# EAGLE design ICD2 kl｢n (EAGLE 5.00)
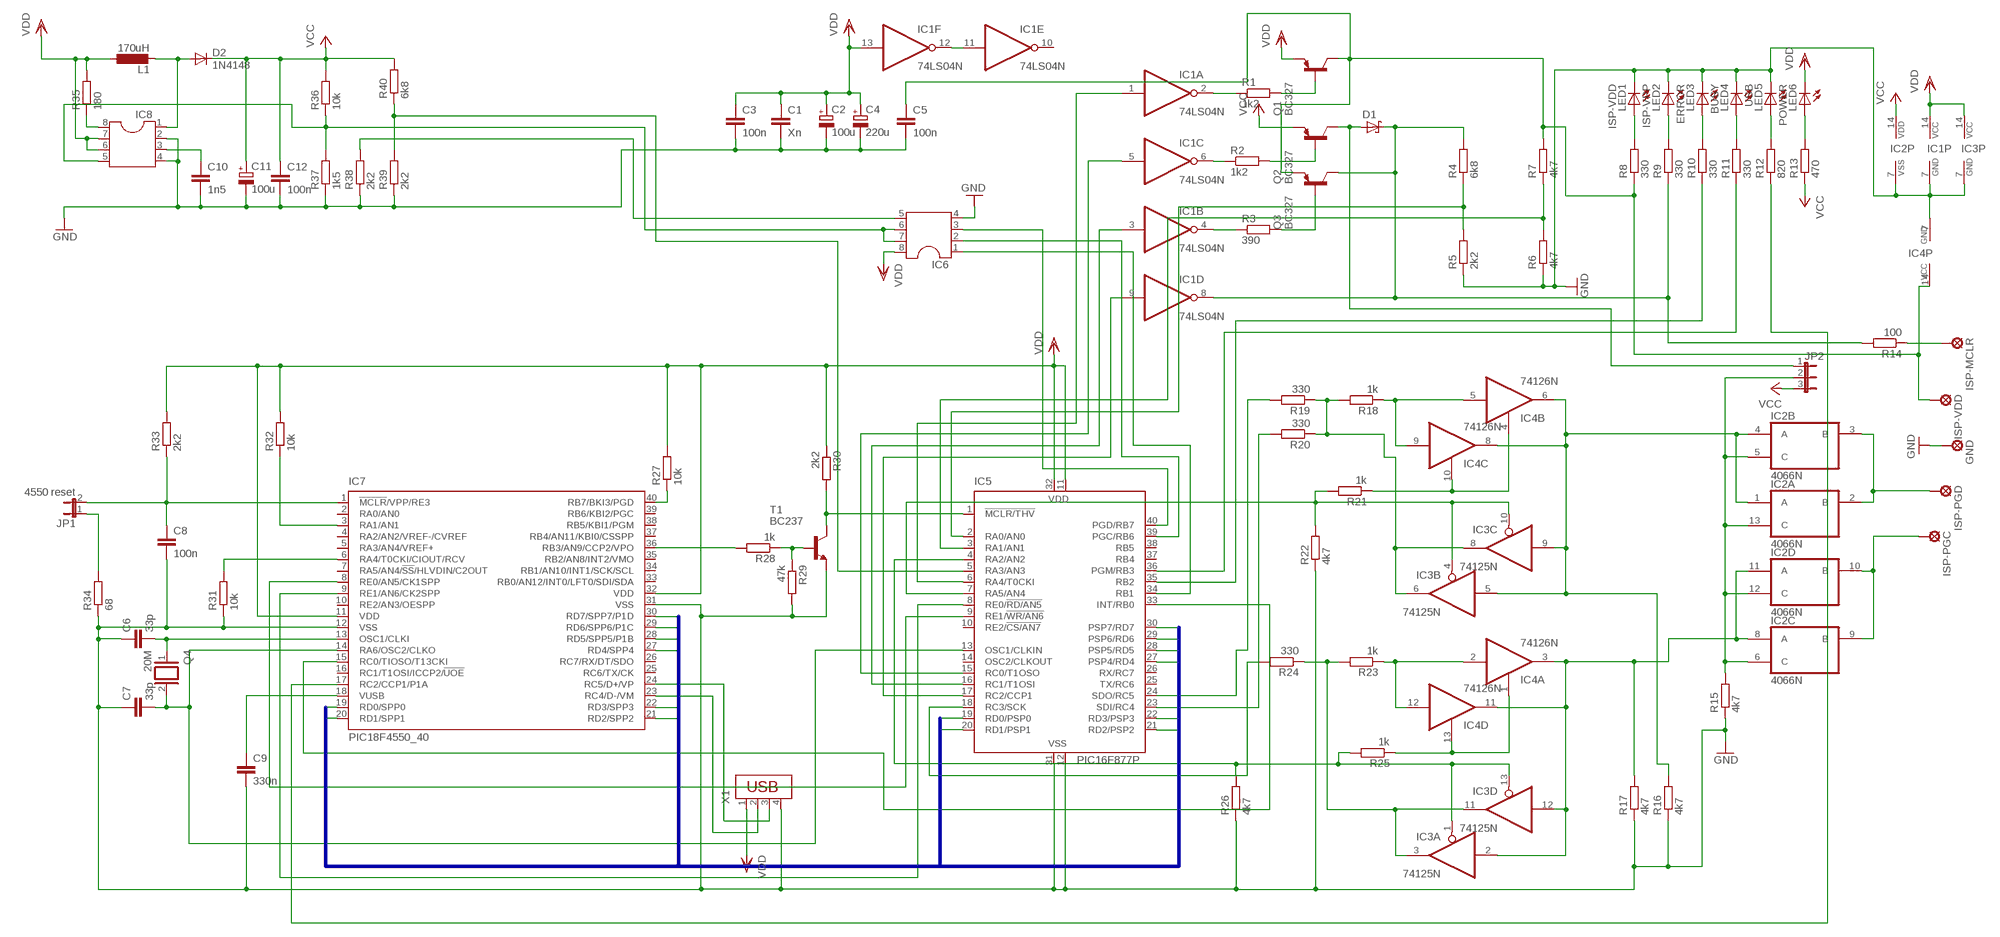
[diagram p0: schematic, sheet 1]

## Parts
C1  Xn  C5/3.5  [C5B3.5]
C2  100u  CPOL-EUE5-6  [E5-6]
C3  100n  C5/3.5  [C5B3.5]
C4  220u  CPOL-EUE5-6  [E5-6]
C5  100n  C5/3.5  [C5B3.5]
C6  33p  C5/3.5  [C5B3.5]
C7  33p  C5/3.5  [C5B3.5]
C8  100n  C5/3.5  [C5B3.5]
C9  330n  C5/3.5  [C5B3.5]
C10  1n5  C5/3.5  [C5B3.5]
C11  100u  CPOL-EUE5-6  [E5-6]
C12  100n  C5/3.5  [C5B3.5]
D1  SCHOTTKY-DIODEF126Z12  [F126Z12]
D2  1N4148  [DO35-10]
GND  LSP11  [LSP11]
IC1  74LS04N  [DIL14]
IC2  4066N  [DIL14]
IC3  74125N  [DIL14]
IC4  74126N  [DIL14]
IC5  PIC16F877P  [DIL40]
IC6  DIL8  [DIL08]
IC7  PIC18F4550_40  [DIL40]
IC8  DIL8  [DIL08]
ISP-MCLR  LSP11  [LSP11]
ISP-PGC  LSP11  [LSP11]
ISP-PGD  LSP11  [LSP11]
ISP-VDD  LSP11  [LSP11]
JP1  4550 reset  JP1E  [JP1]
JP2  JP2E  [JP2]
L1  170uH  L-EU0207/10  [0207/10]
LED1  ISP-VDD  LED5MM  [LED5MM]
LED2  ISP-VPP  LED5MM  [LED5MM]
LED3  ERROR  LED5MM  [LED5MM]
LED4  BUSY  LED5MM  [LED5MM]
LED5  USB  LED5MM  [LED5MM]
LED6  POWER  LED5MM  [LED5MM]
Q1  BC327  [TO92-EBC]
Q2  BC327  [TO92-EBC]
Q3  BC327  [TO92-EBC]
Q4  20M  XTAL/S  [QS]
R1  1k2  R-EU_0207/10  [0207/10]
R2  1k2  R-EU_0207/10  [0207/10]
R3  390  R-EU_0207/10  [0207/10]
R4  6k8  R-EU_0207/10  [0207/10]
R5  2k2  R-EU_0207/10  [0207/10]
R6  4k7  R-EU_0207/10  [0207/10]
R7  4k7  R-EU_0207/10  [0207/10]
R8  330  R-EU_0207/10  [0207/10]
R9  330  R-EU_0207/10  [0207/10]
R10  330  R-EU_0207/10  [0207/10]
R11  330  R-EU_0207/10  [0207/10]
R12  820  R-EU_0207/10  [0207/10]
R13  470  R-EU_0207/10  [0207/10]
R14  100  R-EU_0207/10  [0207/10]
R15  4k7  R-EU_0207/10  [0207/10]
R16  4k7  R-EU_0207/10  [0207/10]
R17  4k7  R-EU_0207/10  [0207/10]
R18  1k  R-EU_0207/10  [0207/10]
R19  330  R-EU_0207/10  [0207/10]
R20  330  R-EU_0207/10  [0207/10]
R21  1k  R-EU_0207/10  [0207/10]
R22  4k7  R-EU_0207/10  [0207/10]
R23  1k  R-EU_0207/10  [0207/10]
R24  330  R-EU_0207/10  [0207/10]
R25  1k  R-EU_0207/10  [0207/10]
R26  4k7  R-EU_0207/10  [0207/10]
R27  10k  R-EU_0207/10  [0207/10]
R28  1k  R-EU_0207/10  [0207/10]
R29  47k  R-EU_0207/10  [0207/10]
R30  2k2  R-EU_0207/10  [0207/10]
R31  10k  R-EU_0207/10  [0207/10]
R32  10k  R-EU_0207/10  [0207/10]
R33  2k2  R-EU_0207/10  [0207/10]
R34  68  R-EU_0207/10  [0207/10]
R35  180  R-EU_0207/10  [0207/10]
R36  10k  R-EU_0207/10  [0207/10]
R37  1k5  R-EU_0207/10  [0207/10]
R38  2k2  R-EU_0207/10  [0207/10]
R39  2k2  R-EU_0207/10  [0207/10]
R40  6k8  R-EU_0207/10  [0207/10]
T1  BC237  [TO92]
X1  USB-787616  [USB]

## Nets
GND: C1.2 C2.- C3.2 C4.- C5.2 C6.1 C7.1 C8.2 C9.2 C10.2 C11.- C12.2 GND.MP IC1.7(P:GND) IC2.7(P:VSS) IC3.7(P:GND) IC4.7(P:GND) IC5.12(VSS) IC5.31(VSS) IC6.4 IC7.12(VSS) IC7.31(VSS) IC8.2 IC8.4 LED1.K(C) LED2.K(C) LED3.K(C) LED4.K(C) LED5.K(C) R5.1 R6.1 R15.1 R16.1 R17.1 R22.1 R26.1 R29.2 R31.1 R34.1 R37.1 R38.1 R39.1 T1.1(E) X1.4
N$1: IC1.2(A:O) R1.1
N$2: IC1.6(C:O) R2.1
N$3: IC1.4(B:O) R3.1
N$4: Q3.B R3.2
N$5: Q2.B R2.2
N$6: Q1.B R1.2
N$7: D1.A JP2.1 Q2.C
N$8: D1.C IC1.8(D:O) Q3.C R4.2 R9.1 R14.2
N$9: ISP-MCLR.MP R14.1
N$10: IC5.2(RA0/AN0) R4.1 R5.2
N$11: IC5.3(RA1/AN1) R6.2 R7.1
N$12: C5.1 IC4.14(P:VCC) ISP-VDD.MP Q1.C Q3.E R7.2 R8.1
N$13: LED1.A R8.2
N$14: LED2.A R9.2
N$15: LED3.A R10.2
N$16: LED4.A R11.2
N$17: LED5.A R12.2
N$18: LED6.A R13.2
N$19: IC4.2(A:I) IC4.12(D:I) R23.1
N$20: IC2.2(A:B) IC2.3(B:B) ISP-PGD.MP
N$21: IC2.9(C:B) IC2.10(D:B) ISP-PGC.MP
N$22: IC2.8(C:A) IC2.11(D:A) IC3.2(A:I) IC3.12(D:I) IC4.3(A:O) IC4.11(D:O) R17.2
N$23: IC2.5(B:C) IC2.6(C:C) IC2.12(D:C) IC2.13(A:C) JP2.2 R15.2
N$24: IC2.1(A:A) IC2.4(B:A) IC3.5(B:I) IC3.9(C:I) IC4.6(B:O) IC4.8(C:O) R16.2
N$25: IC3.6(B:O) IC3.8(C:O) R18.2 R19.1 R20.1
N$26: IC4.5(B:I) IC4.9(C:I) R18.1
N$27: IC3.3(A:O) IC3.11(D:O) R23.2 R24.1
N$28: IC4.4(B:OE) IC4.10(C:OE) R21.1
N$29: IC3.4(B:OE) IC3.10(C:OE) IC5.7(RA5/AN4) R21.2 R22.2
N$30: IC1.11(E:I) IC1.12(F:O)
N$31: IC4.1(A:OE) IC4.13(D:OE) R25.1
N$32: IC5.35(RB2) R10.1
N$33: IC5.36(PGM/RB3) R11.1
N$34: IC3.1(A:OE) IC3.13(D:OE) IC5.4(RA2/AN2) R25.2 R26.2
N$35: IC5.33(INT/RB0) IC7.15(RC0/TIOSO/T13CKI)
N$36: IC5.18(RC3/SCK) R24.2
N$37: IC5.23(SDI/RC4) R20.2
N$38: IC5.24(SDO/RC5) R19.2
N$39: IC1.9(D:I) IC5.17(RC2/CCP1)
N$40: IC1.3(B:I) IC5.16(RC1/T1OSI)
N$41: IC1.5(C:I) IC5.15(RC0/T1OSO)
N$42: IC1.1(A:I) IC5.6(RA4/T0CKI)
N$43: IC7.40(RB7/BKI3/PGD) R27.1
N$45: IC5.1(!MCLR/THV) R30.2 T1.3(C)
N$46: IC5.5(RA3/AN3) R39.2 R40.1
N$47: R28.1 R29.1 T1.2(B)
N$48: IC7.36(RB3/AN9/CCP2/VPO) R28.2
N$50: IC5.40(PGD/RB7) IC6.3
N$51: IC5.39(PGC/RB6) IC6.2
N$52: IC5.34(RB1) IC6.1
N$54: IC7.24(RC5/D+/VP) X1.3
N$55: IC7.23(RC4/D-/VM) X1.2
N$56: C9.1 IC7.18(VUSB)
N$58: C7.2 IC5.13(OSC1/CLKIN) IC7.14(RA6/OSC2/CLKO) Q4.2
N$59: C6.2 IC7.13(OSC1/CLKI) Q4.1
N$64: IC7.6(RA4/T0CKI/CIOUT/RCV) R31.2
N$65: IC7.3(RA1/AN1) R32.1
N$66: JP1.1 R34.2
N$67: C8.1 IC7.1(!MCLR!/VPP/RE3) JP1.2 R33.1
N$69: IC5.9(RE1/!WR/AN6) IC7.8(RE0/AN5/CK1SPP)
N$70: IC5.8(RE0/!RD/AN5) IC7.9(RE1/AN6/CK2SPP)
N$71: IC7.17(RC2/CCP1/P1A) R12.1
N$72: IC8.8 R35.1
N$74: D2.A IC8.1 L1.2
N$76: C10.1 IC8.3
N$79: IC6.6 IC6.7 IC8.5 R36.1 R37.2
N$82: IC6.5 R38.2
PSP0: IC5.19(RD0/PSP0) IC7.19(RD0/SPP0)
PSP1: IC5.20(RD1/PSP1) IC7.20(RD1/SPP1)
PSP2: IC5.21(RD2/PSP2) IC7.21(RD2/SPP2)
PSP3: IC5.22(RD3/PSP3) IC7.22(RD3/SPP3)
PSP4: IC5.27(PSP4/RD4) IC7.27(RD4/SPP4)
PSP5: IC5.28(PSP5/RD5) IC7.28(RD5/SPP5/P1B)
PSP6: IC5.29(PSP6/RD6) IC7.29(RD6/SPP6/P1C)
PSP7: IC5.30(PSP7/RD7) IC7.30(RD7/SPP7/P1D)
VCC: C11.+ C12.1 D2.C IC2.14(P:VDD) JP2.3 Q2.E R13.1 R36.2 R40.2
VDD: C1.1 C2.+ C3.1 C4.+ IC1.13(F:I) IC1.14(P:VCC) IC3.14(P:VCC) IC5.11(VDD) IC5.32(VDD) IC6.8 IC7.11(VDD) IC7.32(VDD) IC8.6 IC8.7 L1.1 LED6.K(C) Q1.E R27.2 R30.1 R32.2 R33.2 R35.2 X1.1
Unconnected: IC1.10(E:O) IC5.10(RE2/!CS/AN7) IC5.14(OSC2/CLKOUT) IC5.25(TX/RC6) IC5.26(RX/RC7) IC5.37(RB4) IC5.38(RB5) IC7.2(RA0/AN0) IC7.4(RA2/AN2/VREF-/CVREF) IC7.5(RA3/AN4/VREF+) IC7.7(RA5/AN4/!SS!/HLVDIN/C2OUT) IC7.10(RE2/AN3/OESPP) IC7.16(RC1/T1OSI/ICCP2/!UOE) IC7.25(RC6/TX/CK) IC7.26(RC7/RX/DT/SDO) IC7.33(RB0/AN12/INT0/LFT0/SDI/SDA) IC7.34(RB1/AN10/INT1/SCK/SCL) IC7.35(RB2/AN8/INT2/VMO) IC7.37(RB4/AN11/KBI0/CSSPP) IC7.38(RB5/KBI1/PGM) IC7.39(RB6/KBI2/PGC)

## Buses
EN,PSP[0..7]

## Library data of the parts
C1 C3 C5-C10 C12 = capacitor-wima:C: CAPACITOR
C2 C4 C11 = rcl:CPOL-EU: POLARIZED CAPACITOR, European symbol
D1 = diode:SCHOTTKY-DIODE: Schottky Diode
D2 = diode:1N4148: DIODE
GND ISP-MCLR ISP-PGC ISP-PGD ISP-VDD = solpad:LSP11: SOLDER PAD
IC1 = 74xx-eu:74*04: Hex INVERTER
IC2 = 40xx:4066: Quad bilateral ANALOG SWITCH
IC3 = 74xx-eu:74*125: Quad bus BUFFER, 3-state
IC4 = 74xx-eu:74*126: Quad bus BUFFER, 3-state
IC5 = microchip:PIC16F87*: MICROCONTROLLER
IC6 IC8 = ic-package:DIL8: Dual In Line / Socket
IC7 = microchip:PIC18F4*_40: USB Microcontrollers with nanoWatt Technology High-Performance, Enhanced Flash, 28/40/44-Pin, Source: http://ww1.microchip.com/downloads/en/devicedoc/39632c.pdf
JP1 = jumper:JP1E: JUMPER
JP2 = jumper:JP2E: JUMPER
L1 = rcl:L-EU: INDUCTOR, European symbol
LED1-LED6 = led:LED: LED
Q1-Q3 = transistor-pnp:BC327*: PNP Transistror
Q4 = special:XTAL/S: CRYSTAL
R1-R40 = rcl:R-EU_: RESISTOR, European symbol
T1 = transistor-neu-to92:BC237: NPN TRANSISTOR
X1 = con-amp:USB-787616: AMP connector

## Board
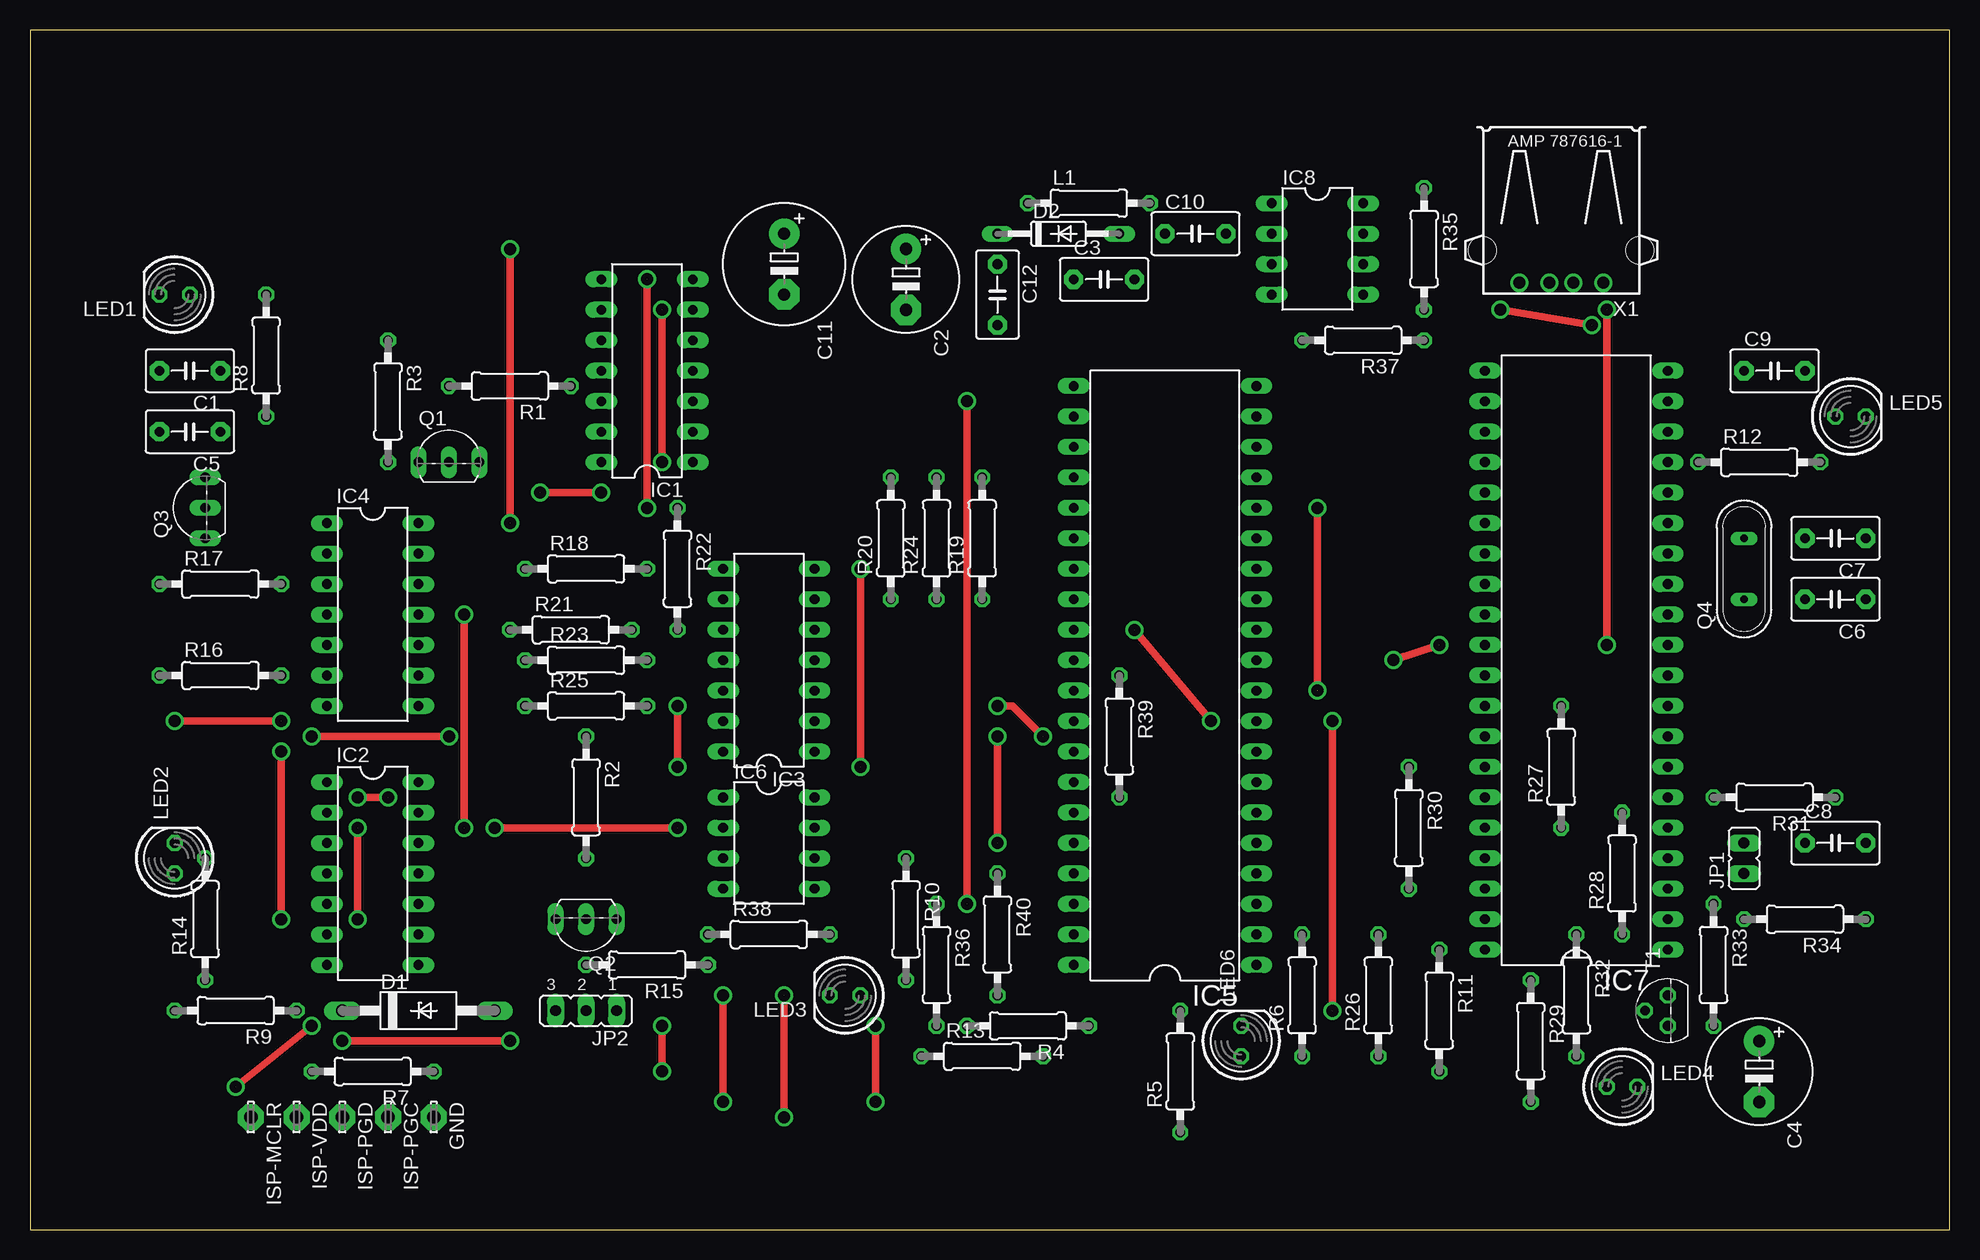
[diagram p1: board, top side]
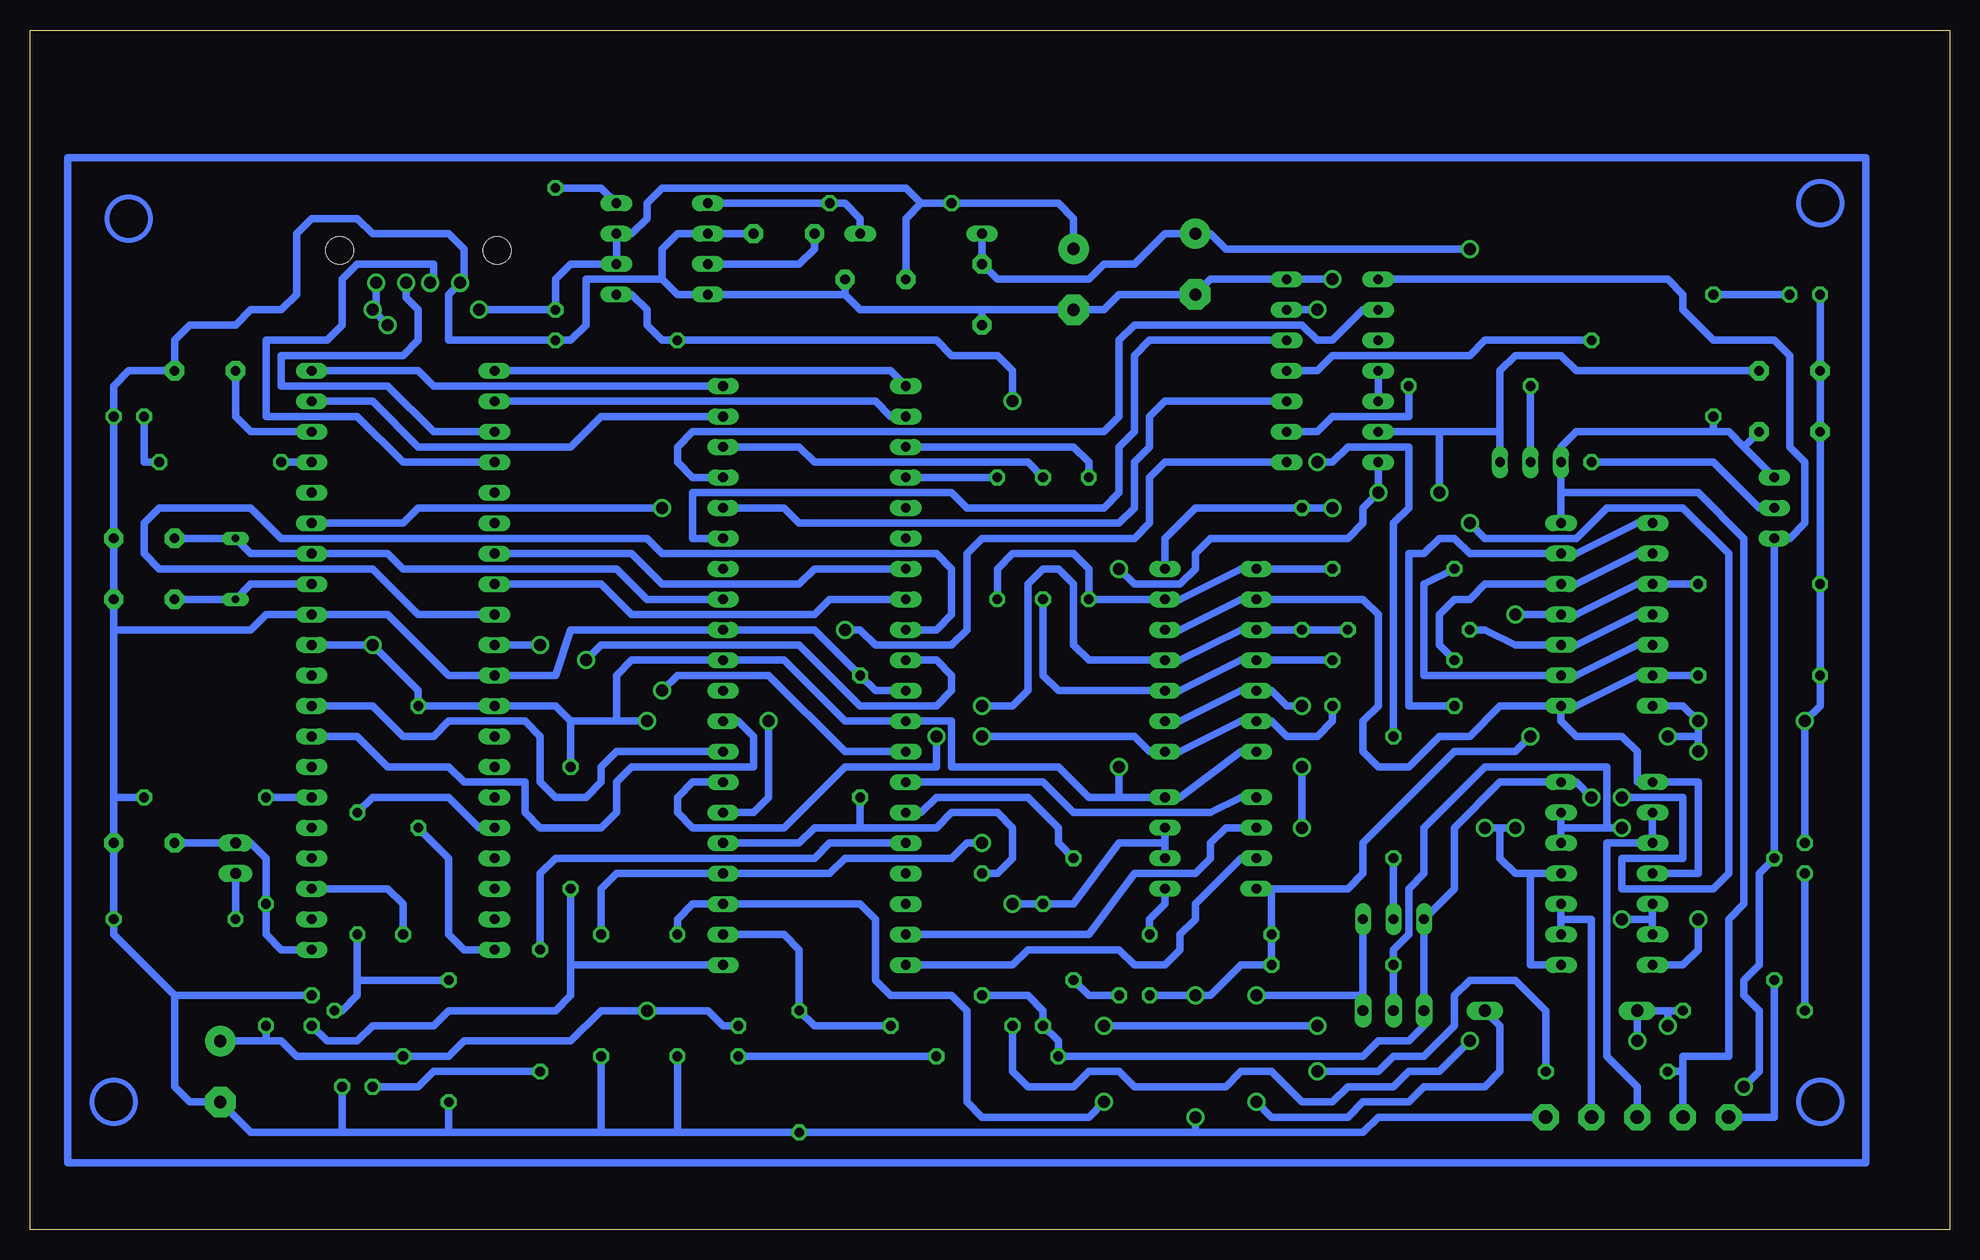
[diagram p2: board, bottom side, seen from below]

Size 160 x 100 mm. Coordinates in mm from the lower left corner, seen from the top.
Outline: 0,0 160,0 160,100 0,100 0,0
Copper layers (1*16): Top 0.035mm / dielectric 1.5mm / Bottom 0.035mm
Design rules "default": minimum track width 10mil, minimum drill 24mil, track to track 8mil, track to pad 8mil, pad to pad 8mil, via to via 8mil, smd to smd 8mil, copper to edge 40mil, drill to drill 8mil, minimum pad ring 10mil, minimum via ring 8mil, stop-mask expansion 4mil, vias tented up to drill 0mil, thermal gap 10mil

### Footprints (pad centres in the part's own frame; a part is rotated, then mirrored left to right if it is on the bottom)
C5B3.5 = drill 0.813 pad 1.6 octagon: 1 -2.54,0; 2 2.54,0
E5-8,5 = drill 1.016 pad 2.54 round: + -2.54,0 | drill 1.016 pad 2.54 octagon: - 2.54,0
E5-10,5 = drill 1.016 pad 2.54 round: + -2.54,0 | drill 1.016 pad 2.54 octagon: - 2.54,0
F126Z12 = drill 1.016 long: A 6.35,0; C -6.35,0
DO35-10 = drill 0.813 long: A 5.08,0; C -5.08,0
LSP11 = drill 1.118 pad 2.159 octagon: MP 0,0
DIL14 = drill 0.813 long: 1 -7.62,-3.81; 2 -5.08,-3.81; 3 -2.54,-3.81; 4 0,-3.81; 5 2.54,-3.81; 6 5.08,-3.81; 7 7.62,-3.81; 8 7.62,3.81; 9 5.08,3.81; 10 2.54,3.81; 11 0,3.81; 12 -2.54,3.81; 13 -5.08,3.81; 14 -7.62,3.81
DIL40 = drill 0.813 long: 1 -24.13,-7.62; 2 -21.59,-7.62; 3 -19.05,-7.62; 4 -16.51,-7.62; 5 -13.97,-7.62; 6 -11.43,-7.62; 7 -8.89,-7.62; 8 -6.35,-7.62; 9 -3.81,-7.62; 10 -1.27,-7.62; 11 1.27,-7.62; 12 3.81,-7.62; 13 6.35,-7.62; 14 8.89,-7.62; 15 11.43,-7.62; 16 13.97,-7.62; 17 16.51,-7.62; 18 19.05,-7.62; 19 21.59,-7.62; 20 24.13,-7.62; 21 24.13,7.62; 22 21.59,7.62; 23 19.05,7.62; 24 16.51,7.62; 25 13.97,7.62; 26 11.43,7.62; 27 8.89,7.62; 28 6.35,7.62; 29 3.81,7.62; 30 1.27,7.62; 31 -1.27,7.62; 32 -3.81,7.62; 33 -6.35,7.62; 34 -8.89,7.62; 35 -11.43,7.62; 36 -13.97,7.62; 37 -16.51,7.62; 38 -19.05,7.62; 39 -21.59,7.62; 40 -24.13,7.62
DIL08 = drill 0.813 long: 1 -3.81,-3.81; 2 -1.27,-3.81; 3 1.27,-3.81; 4 3.81,-3.81; 5 3.81,3.81; 6 1.27,3.81; 7 -1.27,3.81; 8 -3.81,3.81
JP1 = drill 0.914 long: 1 0,-1.27; 2 0,1.27
JP2 = drill 0.914 long: 1 -2.54,0; 2 0,0; 3 2.54,0
0207/10 = drill 0.813 octagon: 1 -5.08,0; 2 5.08,0
LED5MM = drill 0.813 octagon: A -1.27,0; K 1.27,0
TO92-EBC = drill 0.813 long: B 0,-1.27; C -2.54,-1.27; E 2.54,-1.27
QS = drill 0.61 long: 1 -2.54,0; 2 2.54,0
TO92 = drill 0.813 octagon: 1 1.27,0; 2 0,1.905; 3 -1.27,0
USB = drill 1 round: 1 -3.5,12.99; 2 -1,12.99; 3 1,12.99; 4 3.5,12.99 | hole 2.3: -6.57,10.28; 6.57,10.28

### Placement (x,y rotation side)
C1  13.33,71.59 180 top
C2  100u  [E5-8,5]  73.02,79.21 270 top
C3  89.53,79.21 0 top
C4  220u  [E5-8,5]  144.14,13.17 270 top
C5  13.33,66.51 180 top
C6  150.49,52.54 180 top
C7  150.49,57.62 180 top
C8  150.49,32.22 0 top
C9  145.41,71.59 0 top
C10  97.15,83.02 0 top
C11  100u  [E5-10,5]  62.86,80.48 270 top
C12  80.64,77.94 270 top
D1  32.38,18.25 0 top
D2  85.72,83.02 0 top
GND  33.65,9.36 270 top
IC1  51.43,71.59 90 top
IC2  28.57,29.68 270 top
IC3  61.59,47.46 90 top
IC4  28.57,51.27 270 top
IC5  94.61,46.19 90 top
IC6  61.59,32.22 270 top
IC7  128.9,47.46 90 top
IC8  107.31,81.75 270 top
ISP-MCLR  18.41,9.36 270 top
ISP-PGC  29.84,9.36 270 top
ISP-PGD  26.03,9.36 270 top
ISP-VDD  22.22,9.36 270 top
JP1  142.87,30.95 0 top
JP2  46.35,18.25 180 top
L1  88.26,85.56 0 top
LED1  12.06,77.94 180 top
LED2  12.06,30.95 90 top
LED3  67.94,19.52 180 top
LED4  132.71,11.9 0 top
LED5  151.76,67.78 0 top
LED6  100.96,15.71 90 top
Q1  34.92,65.24 0 top
Q2  46.35,24.6 180 top
Q3  13.33,60.16 90 top
Q4  142.87,55.08 90 top
R1  40,70.32 180 top
R2  46.35,36.03 270 top
R3  29.84,69.05 270 top
R4  83.18,16.98 180 top
R5  95.88,13.17 90 top
R6  106.04,19.52 90 top
R7  28.57,13.17 180 top
R8  19.68,72.86 90 top
R9  17.14,18.25 180 top
R10  73.02,25.87 270 top
R11  117.47,18.25 270 top
R12  144.14,63.97 0 top
R13  79.37,14.44 0 top
R14  14.6,25.87 90 top
R15  51.43,22.06 180 top
R16  15.87,46.19 0 top
R17  15.87,53.81 0 top
R18  46.35,55.08 0 top
R19  79.37,57.62 90 top
R20  71.75,57.62 90 top
R21  45.08,50 0 top
R22  53.97,55.08 270 top
R23  46.35,47.46 0 top
R24  75.56,57.62 90 top
R25  46.35,43.65 0 top
R26  112.39,19.52 90 top
R27  127.63,38.57 90 top
R28  132.71,29.68 90 top
R29  125.09,15.71 270 top
R30  114.93,33.49 270 top
R31  145.41,36.03 180 top
R32  128.9,19.52 270 top
R33  140.33,22.06 270 top
R34  147.95,25.87 180 top
R35  116.2,81.75 270 top
R36  75.56,22.06 270 top
R37  111.12,74.13 180 top
R38  61.59,24.6 0 top
R39  90.8,41.11 270 top
R40  80.64,24.6 270 top
T1  136.52,18.25 90 top
X1  127.63,91.91 180 top

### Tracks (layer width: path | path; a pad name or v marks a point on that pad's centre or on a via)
GND  (via drill 1)  (3 unrouted)
  Top 0.61: v12.06,42.38 20.95,42.38 | v20.95,25.87 v20.95,39.84 | v23.49,41.11 v34.92,41.11 | v62.86,9.36 62.86,19.52 | v51.43,60.16 51.43,79.21
  Bottom 0.61: 153.03,36.03 153.03,50 | 153.03,50 C6.1 C7.1 LED5.K 153.03,70.32 151.76,71.59 C9.2 147.95,74.13 146.68,75.4 142.87,75.4 141.6,76.67 139.06,76.67 137.79,77.94 137.79,83.02 136.52,84.29 132.71,84.29 131.44,83.02 125.09,83.02 123.82,81.75 123.82,79.21 124.11,78.92 | 153.03,50 141.6,50 140.33,51.27 IC7.12 130.17,51.27 125.09,46.19 IC7.31 116.2,46.19 114.93,50 IC5.12 94.61,50 R39.1 89.53,44.92 IC5.31 | 153.03,36.03 R31.1 | IC8.4 100.96,77.94 | 124.11,78.92 125.09,77.94 125.09,74.13 R37.1 114.93,74.13 113.66,75.4 113.66,79.21 107.31,79.21 | 125.09,8.09 R29.2 | 56.51,28.41 IC6.4 | 56.51,28.41 R38.1 R15.1 59.05,22.06 61.59,19.52 62.86,19.52 LED3.K | 124.11,78.92 X1.4 | 153.03,36.03 C8.2 R34.1 153.03,24.6 147.95,19.52 | 147.95,19.52 T1.1 | 125.09,8.09 133.98,8.09 | 147.95,19.52 147.95,11.9 146.68,10.63 C4.- 141.6,8.09 133.98,8.09 | 133.98,8.09 LED4.K | 106.04,8.09 R5.1 62.86,8.09 | 106.04,8.09 112.39,8.09 | 112.39,8.09 125.09,8.09 | 112.39,8.09 R26.1 | 107.31,79.21 106.04,77.94 IC8.4 | 107.31,79.21 107.31,81.75 106.04,83.02 IC8.2 C10.2 | IC8.4 92.07,77.94 | 92.07,77.94 C3.2 | 80.64,76.67 90.8,76.67 92.07,77.94 | 80.64,76.67 C2.- 70.48,76.67 69.21,77.94 C11.- 61.59,79.21 IC1.7 51.43,79.21 | v34.92,41.11 36.19,39.84 41.27,39.84 48.89,32.22 48.89,29.68 50.16,28.41 56.51,28.41 | LED2.K v12.06,42.38 10.79,43.65 R16.1 R17.1 C5.2 C1.2 LED1.K | IC4.7 22.22,43.65 20.95,42.38 20.95,41.11 | IC2.7 22.22,22.06 20.95,23.33 v20.95,25.87 | v20.95,39.84 20.95,41.11 | 20.95,41.11 v23.49,41.11 | 80.64,76.67 C12.2 | 62.86,8.09 v62.86,9.36 | 62.86,8.09 48.89,8.09 47.62,9.36 GND.MP | 106.04,8.09 R6.1 | v51.43,60.16 R22.1 62.86,60.16 65.4,57.62 IC3.7
N$1
  Bottom 0.61: IC1.2 52.7,66.51 51.43,67.78 45.08,67.78 R1.1
N$2  (via drill 1)  (1 unrouted)
  Top 0.61: v52.7,63.97 52.7,76.67
  Bottom 0.61: R2.1 46.35,58.89 45.08,60.16 45.08,65.24 50.16,65.24 51.43,63.97 v52.7,63.97 | 52.7,76.67 IC1.6
N$3
  Bottom 0.61: IC1.4 52.7,71.59 51.43,72.86 40,72.86 38.73,74.13 R3.1
N$4
  Bottom 0.61: Q3.B 15.87,60.16 19.68,63.97 R3.2
N$5
  Bottom 0.61: Q2.B R2.2
N$6
  Bottom 0.61: Q1.B R1.2
N$7  (via drill 1)
  Top 0.61: v57.78,10.63 v57.78,19.52
  Bottom 0.61: 48.89,19.52 Q2.C | 48.89,19.52 JP2.1 | v57.78,19.52 48.89,19.52 | v57.78,10.63 56.51,9.36 50.16,9.36 48.89,10.63 45.08,10.63 43.81,11.9 38.73,11.9 37.46,13.17 37.46,16.98 D1.A
N$8  (via drill 1)  (2 unrouted)
  Top 0.61: 17.14,11.9 v23.49,16.98 | v26.03,15.71 40,15.71
  Bottom 0.61: 23.49,18.25 D1.C v26.03,15.71 | R4.2 78.1,13.17 76.83,11.9 73.02,11.9 71.75,13.17 69.21,13.17 67.94,11.9 60.32,11.9 59.05,13.17 56.51,13.17 53.97,10.63 51.43,10.63 50.16,11.9 46.35,11.9 45.08,13.17 42.54,13.17 40,15.71 | 17.14,11.9 15.87,13.17 15.87,18.25 17.14,19.52 17.14,20.79 15.87,22.06 15.87,29.68 R14.2 Q3.C 13.33,57.62 12.06,58.89 12.06,63.97 13.33,65.24 13.33,72.86 14.6,74.13 19.68,74.13 22.22,76.67 22.22,77.94 23.49,79.21 IC1.8 | 23.49,18.25 R9.1 | v23.49,16.98 23.49,18.25
N$9
  Bottom 0.61: ISP-MCLR.MP 14.6,9.36 R14.1
N$10
  Bottom 0.61: IC5.2 97.15,24.6 95.88,23.33 R5.2 94.61,16.98 R4.1
N$11  (via drill 1)  (1 unrouted)
  Top 0.61: v52.7,13.17 v52.7,16.98 | v70.48,16.98 70.48,10.63
  Bottom 0.61: R7.1 33.65,18.25 36.19,20.79 40,20.79 41.27,19.52 41.27,16.98 43.81,14.44 46.35,14.44 47.62,13.17 v52.7,13.17 | R6.2 106.04,25.87 104.77,27.14 IC5.3 90.8,27.14 89.53,25.87 89.53,20.79 88.26,19.52 83.18,19.52 81.91,18.25 81.91,10.63 80.64,9.36 71.75,9.36 70.48,10.63 | v52.7,16.98 v70.48,16.98
N$12
  Bottom 0.61: 32.38,61.43 IC4.14 | 32.38,61.43 20.95,61.43 17.14,57.62 17.14,27.14 18.41,25.87 18.41,14.44 22.22,14.44 22.22,13.17 | ISP-VDD.MP 22.22,13.17 | 22.22,13.17 R7.2 | 32.38,61.43 Q1.C 32.38,65.24 31.11,66.51 19.68,66.51 | 17.14,65.24 18.41,66.51 19.68,66.51 | Q3.E 17.14,65.24 | 17.14,65.24 C5.1 | 19.68,66.51 R8.1
N$13
  Bottom 0.61: LED1.A R8.2
N$14
  Bottom 0.61: R9.2 LED2.A
N$15
  Bottom 0.61: LED3.A 71.75,19.52 R10.2
N$16
  Bottom 0.61: LED4.A 127.63,11.9 126.36,13.17 R11.2
N$17
  Bottom 0.61: R12.2 150.49,63.97 LED5.A
N$18
  Bottom 0.61: R13.2 LED6.A
N$19
  Bottom 0.61: IC4.2 26.03,56.35 31.11,53.81 IC4.12 38.73,53.81 40,52.54 41.27,52.54 42.54,51.27 42.54,48.73 R23.1
N$20
  Bottom 0.61: IC2.2 IC2.3 28.57,32.22 28.57,14.44 26.03,11.9 ISP-PGD.MP
N$21
  Bottom 0.61: 32.38,25.87 IC2.9 | 32.38,25.87 IC2.10 | ISP-PGC.MP 29.84,25.87 32.38,25.87
N$22  (via drill 1)  (2 unrouted)
  Top 0.61: 36.19,33.49 v36.19,51.27 | v38.73,33.49 53.97,33.49 | v53.97,38.57 v53.97,43.65
  Bottom 0.61: IC3.2 64.13,42.38 59.05,44.92 IC3.12 56.51,44.92 55.24,43.65 v53.97,43.65 | IC2.8 34.92,22.06 34.92,29.68 | R17.2 IC4.3 26.03,53.81 31.11,51.27 IC4.11 v36.19,51.27 | 34.92,29.68 IC2.11 | 37.46,33.49 36.19,33.49 | 37.46,33.49 v38.73,33.49 | 53.97,33.49 v53.97,38.57 | 37.46,33.49 37.46,30.95 36.19,29.68 34.92,29.68
N$23  (via drill 1)  (1 unrouted)
  Top 0.61: v27.3,25.87 27.3,33.49
  Bottom 0.61: IC2.6 24.76,25.87 | 32.38,33.49 IC2.13 | JP2.2 R15.2 46.35,23.33 45.08,24.6 45.08,28.41 43.81,29.68 43.81,33.49 38.73,38.57 28.57,38.57 28.57,33.49 | 32.38,33.49 IC2.12 | 28.57,33.49 32.38,33.49 | 24.76,25.87 IC2.5 | 24.76,25.87 v27.3,25.87 | 27.3,33.49 28.57,33.49
N$24
  Bottom 0.61: IC4.8 31.11,43.65 26.03,46.19 IC4.6 R16.2 | IC3.5 64.13,50 59.05,52.54 IC3.9 48.89,52.54 47.62,51.27 47.62,43.65 48.89,42.38 48.89,39.84 47.62,38.57 45.08,38.57 42.54,41.11 40,41.11 37.46,43.65 IC4.8 | IC2.4 20.95,29.68 20.95,37.3 IC2.1 26.03,37.3 26.03,39.84 27.3,41.11 31.11,41.11 32.38,42.38 IC4.8
N$25
  Bottom 0.61: R18.2 IC3.8 59.05,55.08 64.13,52.54 IC3.6 R20.1 71.75,55.08 73.02,56.35 78.1,56.35 79.37,55.08 R19.1
N$26
  Bottom 0.61: IC4.5 26.03,48.73 31.11,46.19 IC4.9 43.81,46.19 43.81,53.81 R18.1
N$27
  Bottom 0.61: R23.2 IC3.11 59.05,47.46 64.13,44.92 IC3.3 74.29,44.92 75.56,46.19 R24.1
N$28
  Bottom 0.61: IC4.4 26.03,51.27 31.11,48.73 IC4.10 36.19,48.73 38.73,50 R21.1
N$29  (via drill 1)  (1 unrouted)
  Top 0.61: v80.64,43.65 81.91,43.65 84.45,41.11
  Bottom 0.61: IC5.7 104.77,37.3 106.04,36.03 106.04,34.76 104.77,33.49 97.15,33.49 92.07,38.57 84.45,38.57 84.45,41.11 | R21.2 R22.2 IC3.10 59.05,50 64.13,47.46 IC3.4 71.75,47.46 73.02,48.73 73.02,53.81 74.29,55.08 75.56,55.08 76.83,53.81 76.83,44.92 78.1,43.65 v80.64,43.65
N$30
  Bottom 0.61: IC1.12 IC1.11
N$31
  Bottom 0.61: IC4.1 26.03,58.89 31.11,56.35 IC4.13 40,56.35 41.27,57.62 42.54,57.62 43.81,56.35 45.08,56.35 45.08,43.65 R25.1
N$32
  Bottom 0.61: IC5.35 85.72,34.76 84.45,36.03 76.83,36.03 74.29,33.49 74.29,32.22 R10.1
N$33
  Bottom 0.61: IC5.36 93.34,32.22 94.61,30.95 116.2,30.95 117.47,29.68 R11.1
N$34  (via drill 1)  (1 unrouted)
  Top 0.61: v80.64,41.11 80.64,32.22
  Bottom 0.61: R26.2 112.39,28.41 111.12,29.68 IC5.4 93.34,29.68 92.07,30.95 83.18,30.95 81.91,32.22 80.64,32.22 | v80.64,41.11 67.94,41.11 66.67,39.84 IC3.1 64.13,39.84 59.05,42.38 IC3.13 56.51,42.38 55.24,41.11 52.7,41.11 51.43,42.38 R25.2
N$35  (via drill 1)  (1 unrouted)
  Top 0.61: 107.31,44.92 v107.31,60.16
  Bottom 0.61: IC7.15 128.9,58.89 127.63,60.16 v107.31,60.16 | IC5.33 92.07,39.84 98.42,46.19 106.04,46.19 107.31,44.92
N$36
  Bottom 0.61: IC5.18 95.88,65.24 94.61,63.97 76.83,63.97 R24.2
N$37
  Bottom 0.61: IC5.23 73.02,65.24 71.75,63.97 R20.2
N$38
  Bottom 0.61: R19.2 IC5.24
N$39
  Bottom 0.61: IC1.9 48.89,76.67 51.43,74.13 52.7,74.13 53.97,75.4 67.94,75.4 69.21,74.13 69.21,67.78 70.48,66.51 104.77,66.51 106.04,65.24 106.04,63.97 104.77,62.7 IC5.17
N$40
  Bottom 0.61: IC5.16 97.15,60.16 95.88,58.89 69.21,58.89 67.94,60.16 67.94,63.97 66.67,65.24 66.67,67.78 65.4,69.05 IC1.3
N$41
  Bottom 0.61: IC5.15 104.77,57.62 104.77,61.43 83.18,61.43 81.91,60.16 70.48,60.16 69.21,61.43 69.21,65.24 67.94,66.51 67.94,72.86 66.67,74.13 IC1.5
N$42  (via drill 1)  (1 unrouted)
  Top 0.61: v98.42,42.38 92.07,50
  Bottom 0.61: IC5.6 99.69,34.76 98.42,36.03 v98.42,42.38 | 92.07,50 90.8,50 89.53,48.73 83.18,48.73 81.91,50 81.91,56.35 80.64,57.62 67.94,57.62 66.67,58.89 66.67,62.7 65.4,63.97 IC1.1
N$43
  Bottom 0.61: IC7.40 123.82,23.33 125.09,24.6 125.09,30.95 R27.1
N$44  (via drill 1)
  other vias: 80.64,41.11
N$45
  Bottom 0.61: 114.93,22.06 114.93,19.52 116.2,18.25 125.09,18.25 126.36,16.98 131.44,16.98 132.71,15.71 135.25,15.71 T1.3 | 114.93,22.06 R30.2 | IC5.1 114.93,22.06
N$46
  Bottom 0.61: IC5.5 95.88,32.22 94.61,33.49 90.8,33.49 | 90.8,33.49 84.45,33.49 83.18,34.76 79.37,34.76 78.1,33.49 78.1,30.95 79.37,29.68 R40.1 | 90.8,33.49 R39.2
N$47
  Bottom 0.61: R29.1 132.71,20.79 | 132.71,20.79 R28.1 | T1.2 133.98,18.25 132.71,19.52 132.71,20.79
N$48
  Bottom 0.61: IC7.36 122.55,33.49 125.09,36.03 131.44,36.03 R28.2
N$49  (via drill 1)
  other vias: 108.58,42.38
N$50
  Bottom 0.61: IC5.40 78.1,22.06 76.83,23.33 69.21,23.33 67.94,22.06 65.4,22.06 64.13,23.33 64.13,24.6 62.86,25.87 62.86,27.14 59.05,30.95 IC6.3
N$51
  Bottom 0.61: IC5.39 71.75,24.6 67.94,29.68 62.86,29.68 61.59,30.95 61.59,32.22 60.32,33.49 IC6.2
N$52
  Bottom 0.61: IC6.1 59.05,36.03 61.59,34.76 73.02,34.76 75.56,37.3 IC5.34
N$53  (via drill 1)
  other vias: 80.64,32.22
N$54
  Bottom 0.61: IC7.24 128.9,63.97 132.71,67.78 140.33,67.78 140.33,74.13 135.25,74.13 133.98,75.4 133.98,79.21 132.71,80.48 126.36,80.48 126.36,79.21 126.63,78.94 X1.3
N$55
  Bottom 0.61: IC7.23 126.36,66.51 130.17,70.32 139.06,70.32 139.06,72.86 128.9,72.86 127.63,74.13 127.63,76.67 128.63,77.67 X1.2 128.63,78.94
N$56
  Bottom 0.61: IC7.18 141.6,66.51 142.87,67.78 C9.1
N$57  (via drill 1)
  other vias: 84.45,41.11
N$58
  Bottom 0.61: C7.2 Q4.2 141.6,56.35 IC7.14 130.17,56.35 128.9,55.08 111.12,55.08 108.58,52.54 IC5.13
N$59
  Bottom 0.61: C6.2 Q4.1 141.6,53.81 IC7.13
N$60  (via drill 1)
  other vias: 130.17,75.4
N$61  (via drill 1)
  other vias: 80.64,43.65
N$62  (via drill 1)
  other vias: 107.31,44.92
N$63  (via drill 1)
  other vias: 107.31,60.16
N$64
  Bottom 0.61: IC7.6 R31.2
N$65
  Bottom 0.61: IC7.3 130.17,28.41 128.9,27.14 R32.1
N$66
  Bottom 0.61: R34.2 JP1.1
N$67
  Bottom 0.61: C8.1 JP1.2 141.6,32.22 140.33,30.95 R33.1 140.33,24.6 139.06,23.33 IC7.1
N$68  (via drill 1)
  other vias: 78.1,69.05
N$69
  Bottom 0.61: IC5.9 100.96,42.38 99.69,41.11 99.69,38.57 109.85,38.57 111.12,37.3 111.12,34.76 112.39,33.49 117.47,33.49 118.74,34.76 118.74,37.3 123.82,37.3 125.09,38.57 130.17,38.57 132.71,41.11 IC7.8
N$70
  Bottom 0.61: IC5.8 111.12,39.84 112.39,38.57 112.39,37.3 113.66,36.03 116.2,36.03 117.47,37.3 117.47,41.11 118.74,42.38 125.09,42.38 126.36,41.11 128.9,41.11 131.44,43.65 IC7.9
N$71
  Bottom 0.61: IC7.17 R12.1
N$72
  Bottom 0.61: IC8.8 112.39,86.83 R35.1
N$73  (via drill 1)
  other vias: 78.1,27.14
N$74
  Bottom 0.61: IC8.1 L1.2 92.07,85.56 90.8,84.29 D2.A
N$75  (via drill 1)
  other vias: 62.86,9.36
N$76
  Bottom 0.61: IC8.3 95.88,80.48 94.61,81.75 C10.1
N$77  (via drill 1)
  other vias: 62.86,19.52
N$79  (via drill 1)  (1 unrouted)
  Top 0.61: 78.1,27.14 v78.1,69.05
  Bottom 0.61: IC6.6 65.4,32.22 | 65.4,32.22 IC6.7 | 65.4,32.22 69.21,32.22 73.02,27.14 R36.1 78.1,27.14 | IC8.5 109.85,77.94 108.58,76.67 108.58,75.4 107.31,74.13 R37.2 84.45,74.13 83.18,72.86 79.37,72.86 78.1,71.59 v78.1,69.05
N$80  (via drill 1)
  other vias: 42.54,61.43
N$81  (via drill 1)
  other vias: 47.62,61.43
N$82
  Bottom 0.61: IC6.5 65.4,27.14 66.67,25.87 R38.2
N$83  (via drill 1)
  other vias: 40,81.75
N$84  (via drill 1)
  other vias: 69.21,55.08
N$87  (via drill 1)
  other vias: 20.95,42.38
N$88  (via drill 1)
  other vias: 23.49,41.11
N$90  (via drill 1)
  other vias: 52.7,63.97
N$91  (via drill 1)
  other vias: 51.43,79.21
N$92  (via drill 1)
  other vias: 51.43,60.16
N$93  (via drill 1)
  other vias: 57.78,10.63
N$94  (via drill 1)
  other vias: 57.78,19.52
N$95  (via drill 1)
  other vias: 70.48,16.98
N$96  (via drill 1)
  other vias: 70.48,10.63
N$97  (via drill 1)
  other vias: 36.19,51.27
N$98  (via drill 1)
  other vias: 36.19,33.49
N$99  (via drill 1)
  other vias: 12.06,42.38
N$100  (via drill 1)
  other vias: 92.07,50
N$101  (via drill 1)
  other vias: 20.95,39.84
N$102  (via drill 1)
  other vias: 34.92,41.11
N$103  (via drill 1)
  other vias: 52.7,13.17
N$104  (via drill 1)
  other vias: 52.7,16.98
N$105  (via drill 1)
  other vias: 17.14,11.9
N$106  (via drill 1)
  other vias: 23.49,16.98
N$107
  Bottom 0.61: 6.98,5.55 6.98,89.37 156.84,89.37 156.84,5.55 6.98,5.55
N$108  (via drill 1)
  other vias: 27.3,25.87
N$109  (via drill 1)
  other vias: 26.03,15.71
N$110  (via drill 1)
  other vias: 40,15.71
N$111  (via drill 1)
  other vias: 27.3,33.49
N$112  (via drill 1)
  other vias: 27.3,36.03
N$113  (via drill 1)
  other vias: 98.42,42.38
N$114  (via drill 1)
  other vias: 20.95,25.87
N$115  (via drill 1)
  other vias: 29.84,36.03
N$117  (via drill 1)
  other vias: 52.7,76.67
N$118  (via drill 1)
  other vias: 38.73,33.49
N$119  (via drill 1)
  other vias: 113.66,47.46
N$120  (via drill 1)
  other vias: 117.47,48.73
N$122  (via drill 1)
  other vias: 69.21,38.57
N$123  (via drill 1)
  other vias: 108.58,18.25
N$124  (via drill 1)
  other vias: 131.44,76.67
N$125  (via drill 1)
  other vias: 131.44,48.73
N$126  (via drill 1)
  other vias: 122.55,76.67
N$128  (via drill 1)
  other vias: 40,58.89
N$130  (via drill 1)
  other vias: 53.97,33.49
N$131  (via drill 1)
  other vias: 53.97,43.65
N$132  (via drill 1)
  other vias: 53.97,38.57
PSP0
  Bottom 0.61: IC7.19 131.44,69.05 127.63,65.24 114.93,65.24 112.39,67.78 IC5.19
PSP1
  Bottom 0.61: IC7.20 127.63,71.59 126.36,70.32 IC5.20
PSP2
  Bottom 0.61: IC7.21 88.26,71.59 IC5.21
PSP3
  Bottom 0.61: IC7.22 89.53,69.05 88.26,67.78 IC5.22
PSP4
  Bottom 0.61: IC7.27 109.85,56.35 107.31,53.81 95.88,53.81 94.61,55.08 IC5.27
PSP5
  Bottom 0.61: IC7.28 112.39,53.81 109.85,51.27 94.61,51.27 93.34,52.54 IC5.28
PSP6
  Bottom 0.61: IC7.29 127.63,51.27 131.44,55.08 149.22,55.08 150.49,56.35 150.49,58.89 149.22,60.16 141.6,60.16 139.06,57.62 108.58,57.62 107.31,56.35 84.45,56.35 83.18,55.08 83.18,51.27 84.45,50 IC5.29
PSP7  (via drill 1)  (1 unrouted)
  Top 0.61: v113.66,47.46 117.47,48.73
  Bottom 0.61: 117.47,48.73 IC7.30 | v113.66,47.46 112.39,48.73 95.88,48.73 90.8,43.65 84.45,43.65 83.18,44.92 83.18,46.19 84.45,47.46 IC5.30
VCC  (via drill 1)  (2 unrouted)
  Top 0.61: v27.3,36.03 29.84,36.03 | 40,58.89 v40,81.75
  Bottom 0.61: 40,58.89 38.73,57.62 31.11,57.62 28.57,60.16 22.22,60.16 18.41,56.35 18.41,29.68 19.68,28.41 27.3,28.41 27.3,30.95 22.22,30.95 22.22,36.03 v27.3,36.03 | D2.C C12.1 79.37,79.21 71.75,79.21 70.48,80.48 67.94,80.48 65.4,83.02 C11.+ 61.59,83.02 60.32,81.75 v40,81.75 | R40.2 76.83,19.52 75.56,18.25 R36.2 74.29,15.71 R13.1 48.89,14.44 47.62,15.71 45.08,15.71 43.81,16.98 JP2.3 Q2.E 41.27,28.41 41.27,33.49 37.46,37.3 IC2.14 31.11,37.3 29.84,36.03
VDD  (via drill 1)  (5 unrouted)
  Top 0.61: 108.58,18.25 v108.58,42.38 | v131.44,48.73 131.44,76.67 | v122.55,76.67 130.17,75.4 | 42.54,61.43 v47.62,61.43 | v69.21,55.08 69.21,38.57
  Bottom 0.61: 114.93,42.38 R30.1 | IC3.14 59.05,39.84 64.13,36.03 IC6.8 69.21,36.03 | 42.54,66.51 IC1.13 | 140.33,15.71 C4.+ | 140.33,15.71 R33.2 | 140.33,15.71 139.06,15.71 137.79,14.44 R32.2 125.09,14.44 123.82,15.71 114.93,15.71 112.39,18.25 108.58,18.25 103.5,18.25 102.23,16.98 LED6.K | v108.58,42.38 111.12,42.38 | 111.12,42.38 114.93,42.38 | X1.1 131.13,76.98 131.44,76.67 130.17,75.4 | IC7.11 v131.44,48.73 127.63,44.92 R27.2 IC7.32 116.2,43.65 114.93,42.38 | v122.55,76.67 R35.2 116.2,79.21 114.93,80.48 IC8.6 IC8.7 109.85,83.02 108.58,84.29 108.58,85.56 107.31,86.83 86.99,86.83 85.72,85.56 | C3.1 86.99,84.29 85.72,85.56 | 85.72,85.56 L1.1 74.29,85.56 73.02,84.29 C2.+ | 37.46,66.51 37.46,71.59 36.19,72.86 32.38,72.86 31.11,71.59 C1.1 | 37.46,66.51 Q1.E | 69.21,36.03 69.21,38.57 | 37.46,66.51 42.54,66.51 | 42.54,66.51 42.54,61.43 | IC1.14 v47.62,61.43 48.89,60.16 48.89,58.89 50.16,57.62 61.59,57.62 62.86,56.35 62.86,55.08 64.13,53.81 67.94,53.81 v69.21,55.08 | 69.21,36.03 71.75,36.03 74.29,38.57 83.18,38.57 83.18,42.38 IC5.32 92.07,42.38 97.15,47.46 IC5.11 109.85,47.46 111.12,46.19 111.12,42.38
(copper drawn outside any net)
  shapes: Bottom circle x4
